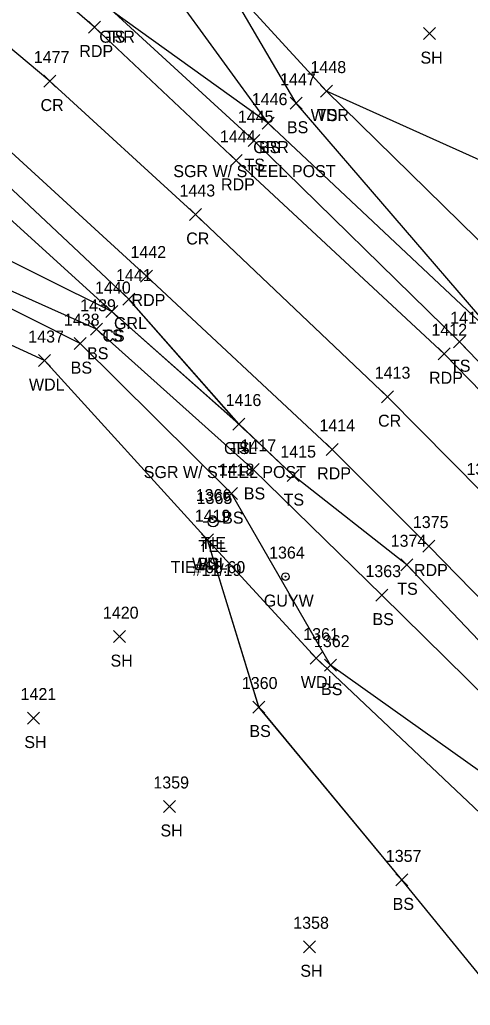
# Model space of a CAD drawing. Extents: x 1415642 to 1422021, y 544543 to 547232.
# Drawn here: x 1416185.4 to 1416260.5, y 546640.6 to 546804.9 of the extents above; entities that cross this region are included whole.
import ezdxf

# ---------------------------------------------------------------- set-up
doc = ezdxf.new("R2010")
doc.units = 0
for name, color, linetype in [('C_A', 7, 'Continuous'), ('C_C', 7, 'Continuous'), ('C_I', 7, 'Continuous'), ('CBP', 7, 'Continuous'), ('L_A', 7, 'Continuous'), ('L_I', 7, 'Continuous'), ('L_TIC', 7, 'Continuous'), ('LAWA', 7, 'Continuous'), ('LELB', 7, 'Continuous'), ('P_A', 7, 'Continuous'), ('P_I', 7, 'Continuous'), ('P_TIC', 7, 'Continuous'), ('PET', 7, 'Continuous'), ('PRC', 7, 'Continuous'), ('R_A', 7, 'Continuous'), ('R_C', 7, 'Continuous'), ('R_I', 7, 'Continuous'), ('R_TIC', 7, 'Continuous'), ('RGR', 7, 'Continuous'), ('U_A', 7, 'Continuous'), ('U_C', 7, 'Continuous'), ('U_I', 7, 'Continuous'), ('UP', 7, 'Continuous'), ('UPGW', 7, 'Continuous')]:
    doc.layers.add(name, color=color, linetype=linetype)

msp = doc.modelspace()

# ---------------------------------------------------------------- linework, layer by layer
at = {"layer": 'CBP'}
for radius in [0.625, 0.0833]:
    msp.add_circle((1416217.49, 546721.65), radius, dxfattribs=at)
at = {"layer": 'L_TIC'}
for points in [[(1416252.67, 546801.58), (1416254.67, 546803.58)], [(1416254.67, 546801.58), (1416252.67, 546803.58)], [(1416235.51, 546792), (1416237.51, 546794)], [(1416237.51, 546792), (1416235.51, 546794)], [(1416235.51, 546792), (1416237.51, 546794)], [(1416237.51, 546792), (1416235.51, 546794)], [(1416230.45, 546789.98), (1416232.45, 546791.98)], [(1416232.45, 546789.98), (1416230.45, 546791.98)], [(1416225.79, 546786.66), (1416227.79, 546788.66)], [(1416227.79, 546786.66), (1416225.79, 546788.66)], [(1416223.41, 546783.74), (1416225.41, 546785.74)], [(1416225.41, 546783.74), (1416223.41, 546785.74)], [(1416199.69, 546755.25), (1416201.69, 546757.25)], [(1416201.69, 546755.25), (1416199.69, 546757.25)], [(1416199.69, 546755.25), (1416201.69, 546757.25)], [(1416201.69, 546755.25), (1416199.69, 546757.25)], [(1416197.14, 546752.3), (1416199.14, 546754.3)], [(1416199.14, 546752.3), (1416197.14, 546754.3)], [(1416194.41, 546749.9), (1416196.41, 546751.9)], [(1416196.41, 546749.9), (1416194.41, 546751.9)], [(1416257.67, 546750.22), (1416259.67, 546752.22)], [(1416259.67, 546750.22), (1416257.67, 546752.22)], [(1416188.47, 546747.09), (1416190.47, 546749.09)], [(1416190.47, 546747.09), (1416188.47, 546749.09)], [(1416220.86, 546736.5), (1416222.86, 546738.5)], [(1416222.86, 546736.5), (1416220.86, 546738.5)], [(1416223.27, 546728.93), (1416225.27, 546730.93)], [(1416225.27, 546728.93), (1416223.27, 546730.93)], [(1416229.93, 546727.9), (1416231.93, 546729.9)], [(1416231.93, 546727.9), (1416229.93, 546729.9)], [(1416219.66, 546724.9), (1416221.66, 546726.9)], [(1416221.66, 546724.9), (1416219.66, 546726.9)], [(1416215.66, 546717.21), (1416217.66, 546719.21)], [(1416217.66, 546717.21), (1416215.66, 546719.21)], [(1416215.66, 546717.21), (1416217.66, 546719.21)], [(1416217.66, 546717.21), (1416215.66, 546719.21)], [(1416248.88, 546713.04), (1416250.88, 546715.04)], [(1416250.88, 546713.04), (1416248.88, 546715.04)], [(1416244.72, 546707.98), (1416246.72, 546709.98)], [(1416246.72, 546707.98), (1416244.72, 546709.98)], [(1416201, 546701.06), (1416203, 546703.06)], [(1416203, 546701.06), (1416201, 546703.06)], [(1416233.79, 546697.48), (1416235.79, 546699.48)], [(1416235.79, 546697.48), (1416233.79, 546699.48)], [(1416236.14, 546696.31), (1416238.14, 546698.31)], [(1416238.14, 546696.31), (1416236.14, 546698.31)], [(1416224.2, 546689.33), (1416226.2, 546691.33)], [(1416226.2, 546689.33), (1416224.2, 546691.33)], [(1416186.63, 546687.49), (1416188.63, 546689.49)], [(1416188.63, 546687.49), (1416186.63, 546689.49)], [(1416209.34, 546672.75), (1416211.34, 546674.75)], [(1416211.34, 546672.75), (1416209.34, 546674.75)], [(1416248.08, 546660.51), (1416250.08, 546662.51)], [(1416250.08, 546660.51), (1416248.08, 546662.51)], [(1416232.64, 546649.36), (1416234.64, 546651.36)], [(1416234.64, 546649.36), (1416232.64, 546651.36)]]:
    msp.add_lwpolyline(points, dxfattribs=at)
at = {"layer": 'LAWA'}
for points in [[(1416278.11, 546774.25), (1416236.51, 546793), (1416219.21, 546811.88)], [(1416278.12, 546774.25), (1416236.51, 546793), (1416219.21, 546811.88)], [(1416366.86, 546544.85), (1416337.81, 546578.41), (1416315.28, 546603.5), (1416281.6, 546646.05), (1416263.12, 546671.71), (1416234.79, 546698.48), (1416216.66, 546718.21), (1416189.47, 546748.09), (1416170.48, 546756.81)], [(1416366.86, 546544.85), (1416337.81, 546578.41), (1416315.28, 546603.5), (1416281.6, 546646.05), (1416263.12, 546671.71), (1416234.8, 546698.48), (1416216.66, 546718.21), (1416189.46, 546748.09), (1416170.49, 546756.81)]]:
    msp.add_lwpolyline(points, dxfattribs=at)
at = {"layer": 'LELB'}
for points in [[(1416200.69, 546756.25), (1416177.76, 546767.63), (1416166.72, 546775.57), (1416158.94, 546780.74), (1416149.8, 546790.95), (1416145.27, 546792.19), (1416135.47, 546803.24), (1416119.09, 546819.38), (1416087.86, 546845.73), (1416058.66, 546867.92), (1416017.63, 546898.15), (1415975.94, 546926.54), (1415961.59, 546937.35), (1415930.25, 546967.22), (1415904.85, 546987.6), (1415883.27, 547005.7), (1415850.56, 547030.99), (1415821.69, 547055.02)], [(1416200.69, 546756.25), (1416177.77, 546767.63), (1416166.72, 546775.57), (1416158.93, 546780.74), (1416149.8, 546790.95), (1416145.28, 546792.19), (1416135.47, 546803.24), (1416119.09, 546819.38), (1416087.87, 546845.73), (1416058.67, 546867.92), (1416017.63, 546898.16), (1415975.95, 546926.55), (1415961.6, 546937.34), (1415930.25, 546967.22), (1415904.86, 546987.6), (1415883.28, 547005.7), (1415850.57, 547030.99), (1415821.7, 547055.02)], [(1416413.88, 546519.84), (1416385.73, 546558.12), (1416356.85, 546595.36), (1416336.82, 546621.39), (1416300.66, 546661.66), (1416278.22, 546684.25), (1416249.88, 546714.04), (1416230.93, 546728.9), (1416221.86, 546737.5), (1416200.69, 546756.25), (1416176.24, 546778.44), (1416157.26, 546793.38), (1416140.02, 546808.9), (1416121.84, 546825.58), (1416090.2, 546848.7), (1416061.67, 546872.28), (1416021.03, 546902.96), (1415979.27, 546932.57), (1415964.6, 546940.59)], [(1416413.88, 546519.84), (1416385.73, 546558.12), (1416356.85, 546595.36), (1416336.82, 546621.39), (1416300.66, 546661.66), (1416278.22, 546684.25), (1416249.88, 546714.04), (1416230.93, 546728.9), (1416221.87, 546737.51), (1416200.69, 546756.25), (1416176.24, 546778.44), (1416157.26, 546793.38), (1416140.03, 546808.9), (1416121.84, 546825.58), (1416090.21, 546848.7), (1416061.68, 546872.28), (1416021.04, 546902.96), (1415979.28, 546932.57), (1415964.61, 546940.59)], [(1416307.15, 546711.36), (1416298.6, 546718.22), (1416262.67, 546753.94), (1416226.79, 546787.66), (1416210.45, 546810.14), (1416201.52, 546824.86), (1416194.8, 546838.18), (1416185.88, 546835.28), (1416179.92, 546838.46), (1416184.98, 546843.17), (1416189.86, 546849.7)], [(1416307.15, 546711.36), (1416298.6, 546718.22), (1416262.67, 546753.94), (1416226.79, 546787.66), (1416210.45, 546810.14), (1416201.53, 546824.86), (1416194.8, 546838.18), (1416185.88, 546835.28), (1416179.92, 546838.45), (1416184.98, 546843.16), (1416189.86, 546849.7)], [(1416313.42, 546715.93), (1416294.82, 546728.93), (1416263.75, 546753.42), (1416231.45, 546790.98), (1416219.21, 546811.88), (1416212.8, 546833.85)], [(1416313.42, 546715.93), (1416294.82, 546728.93), (1416263.75, 546753.42), (1416231.45, 546790.98), (1416219.21, 546811.88), (1416212.8, 546833.84)], [(1416462.64, 546496.11), (1416437.87, 546538.89), (1416411.19, 546576.82), (1416382.17, 546614.17), (1416360.8, 546639.39), (1416323.65, 546683.15), (1416301.53, 546707.03), (1416273.6, 546735.69), (1416258.67, 546751.22), (1416224.41, 546784.74), (1416201.13, 546806.07), (1416169.09, 546832.26)], [(1416462.64, 546496.11), (1416437.87, 546538.89), (1416411.18, 546576.82), (1416382.17, 546614.17), (1416360.8, 546639.39), (1416323.65, 546683.15), (1416301.53, 546707.03), (1416273.6, 546735.69), (1416258.67, 546751.22), (1416224.4, 546784.74), (1416201.13, 546806.07), (1416169.09, 546832.26)], [(1416308.55, 546724.26), (1416297.12, 546732.13), (1416269.94, 546760.18), (1416236.51, 546793)], [(1416308.55, 546724.26), (1416297.12, 546732.13), (1416269.94, 546760.18), (1416236.51, 546793)], [(1416578, 546177.77), (1416578.55, 546199.27), (1416573.9, 546214.14), (1416552.43, 546269), (1416536.22, 546304.5), (1416520.22, 546335.71), (1416500.65, 546371.21), (1416484.25, 546405.14), (1416455.06, 546455.78), (1416435.93, 546486.65), (1416412.14, 546519.01), (1416383.64, 546557.13), (1416352.74, 546592.54), (1416331.82, 546618.14), (1416293.94, 546655.61), (1416274.22, 546680.91), (1416245.72, 546708.98), (1416224.27, 546729.93), (1416198.14, 546753.3), (1416170.94, 546765.48), (1416158.5, 546767.31), (1416141.08, 546772.75), (1416136.01, 546776.95), (1416129, 546780.64)], [(1416578, 546177.77), (1416578.55, 546199.27), (1416573.9, 546214.14), (1416552.42, 546269.01), (1416536.22, 546304.5), (1416520.22, 546335.71), (1416500.65, 546371.22), (1416484.25, 546405.15), (1416455.06, 546455.79), (1416435.93, 546486.65), (1416412.14, 546519.01), (1416383.65, 546557.13), (1416352.74, 546592.54), (1416331.82, 546618.14), (1416293.94, 546655.62), (1416274.22, 546680.91), (1416245.72, 546708.98), (1416224.27, 546729.93), (1416198.14, 546753.3), (1416170.94, 546765.48), (1416158.51, 546767.31), (1416141.09, 546772.75), (1416136.01, 546776.96), (1416129.01, 546780.64)], [(1416503.76, 546247.98), (1416498.74, 546274.69), (1416501.23, 546308.66), (1416502.98, 546324.04), (1416489.47, 546365.32), (1416480.57, 546403.46), (1416453.11, 546455.02), (1416433.2, 546484.78), (1416409.26, 546516.78), (1416378.25, 546552.92), (1416343.61, 546583.91), (1416327.57, 546614.09), (1416289.4, 546651.59), (1416267.58, 546675.69), (1416237.14, 546697.31), (1416220.66, 546725.9), (1416195.41, 546750.9), (1416170.78, 546763.33), (1416158.82, 546764.49), (1416140.16, 546770.72), (1416135.4, 546775.05), (1416128.27, 546778.63)], [(1416503.76, 546247.98), (1416498.74, 546274.69), (1416501.24, 546308.65), (1416502.98, 546324.03), (1416489.47, 546365.32), (1416480.57, 546403.46), (1416453.11, 546455.02), (1416433.2, 546484.78), (1416409.26, 546516.79), (1416378.25, 546552.92), (1416343.61, 546583.91), (1416327.58, 546614.09), (1416289.4, 546651.59), (1416267.58, 546675.69), (1416237.14, 546697.31), (1416220.66, 546725.9), (1416195.42, 546750.9), (1416170.78, 546763.33), (1416158.81, 546764.5), (1416140.16, 546770.72), (1416135.4, 546775.05), (1416128.28, 546778.62)], [(1416315.28, 546603.5), (1416270.97, 546634.69), (1416249.08, 546661.51), (1416225.2, 546690.33), (1416216.66, 546718.21)], [(1416315.28, 546603.5), (1416270.97, 546634.69), (1416249.08, 546661.51), (1416225.21, 546690.34), (1416216.66, 546718.21)]]:
    msp.add_lwpolyline(points, dxfattribs=at)
at = {"layer": 'P_TIC'}
for points in [[(1416196.8, 546802.68), (1416198.8, 546804.68)], [(1416198.8, 546802.68), (1416196.8, 546804.68)], [(1416189.4, 546793.67), (1416191.4, 546795.67)], [(1416191.4, 546793.67), (1416189.4, 546795.67)], [(1416220.42, 546780.44), (1416222.42, 546782.44)], [(1416222.42, 546780.44), (1416220.42, 546782.44)], [(1416213.68, 546771.43), (1416215.68, 546773.43)], [(1416215.68, 546771.43), (1416213.68, 546773.43)], [(1416205.51, 546761.17), (1416207.51, 546763.17)], [(1416207.51, 546761.17), (1416205.51, 546763.17)], [(1416255.1, 546748.21), (1416257.1, 546750.21)], [(1416257.1, 546748.21), (1416255.1, 546750.21)], [(1416245.66, 546741.06), (1416247.66, 546743.06)], [(1416247.66, 546741.06), (1416245.66, 546743.06)], [(1416236.44, 546732.28), (1416238.44, 546734.28)], [(1416238.44, 546732.28), (1416236.44, 546734.28)], [(1416252.58, 546716.16), (1416254.58, 546718.16)], [(1416254.58, 546716.16), (1416252.58, 546718.16)]]:
    msp.add_lwpolyline(points, dxfattribs=at)
at = {"layer": 'PET'}
for points in [[(1416435.56, 546537.44), (1416408.53, 546574.61), (1416379.54, 546611.97), (1416358.62, 546637.86), (1416320.38, 546681.18), (1416299.04, 546704.62), (1416270.68, 546734.26), (1416256.1, 546749.21), (1416221.42, 546781.44), (1416197.8, 546803.68), (1416167.45, 546829.93), (1416146.9, 546847.39), (1416116.66, 546870.72), (1416088.42, 546892.72), (1416062.97, 546911.59), (1416031.6, 546935.61), (1415998.08, 546959.73), (1415969.06, 546981.93), (1415936.64, 547006.92)], [(1416435.56, 546537.44), (1416408.53, 546574.62), (1416379.54, 546611.97), (1416358.63, 546637.85), (1416320.38, 546681.18), (1416299.04, 546704.62), (1416270.69, 546734.26), (1416256.1, 546749.21), (1416221.42, 546781.44), (1416197.8, 546803.68), (1416167.45, 546829.93), (1416146.9, 546847.38), (1416116.66, 546870.72), (1416088.42, 546892.72), (1416062.98, 546911.58), (1416031.6, 546935.61), (1415998.08, 546959.73), (1415969.07, 546981.93), (1415936.65, 547006.92)], [(1416417.68, 546520.98), (1416388.9, 546560.28), (1416359.4, 546597.75), (1416339.06, 546622.92), (1416303.08, 546664.45), (1416282.37, 546687.64), (1416253.58, 546717.16), (1416237.44, 546733.28), (1416206.51, 546762.17), (1416181.86, 546784.67), (1416151.94, 546810.47), (1416130.39, 546828.26), (1416101.49, 546851.34), (1416072.78, 546874.03), (1416047.41, 546892.82), (1416017.81, 546915.59), (1415982.21, 546942.39), (1415954.4, 546964.56)], [(1416417.68, 546520.98), (1416388.9, 546560.28), (1416359.4, 546597.76), (1416339.06, 546622.93), (1416303.08, 546664.45), (1416282.37, 546687.65), (1416253.58, 546717.16), (1416237.44, 546733.28), (1416206.51, 546762.17), (1416181.87, 546784.67), (1416151.94, 546810.47), (1416130.39, 546828.26), (1416101.49, 546851.34), (1416072.78, 546874.03), (1416047.41, 546892.82), (1416017.81, 546915.59), (1415982.21, 546942.39), (1415954.4, 546964.56)]]:
    msp.add_lwpolyline(points, dxfattribs=at)
at = {"layer": 'PRC'}
for points in [[(1416425.29, 546532.23), (1416399.16, 546568.17), (1416370.34, 546605), (1416349.98, 546630.03), (1416312.55, 546673.44), (1416291.21, 546696.63), (1416262.58, 546725.99), (1416246.66, 546742.06), (1416214.68, 546772.43), (1416190.4, 546794.67), (1416160.38, 546819.82), (1416139.01, 546837.64), (1416109.6, 546860.71), (1416080.51, 546883.13), (1416051.44, 546902.01), (1416024.84, 546926.07), (1415989.92, 546951.67), (1415962.46, 546973.18)], [(1416425.29, 546532.24), (1416399.16, 546568.17), (1416370.35, 546605), (1416349.98, 546630.03), (1416312.55, 546673.45), (1416291.21, 546696.63), (1416262.58, 546725.99), (1416246.66, 546742.06), (1416214.67, 546772.43), (1416190.4, 546794.67), (1416160.38, 546819.82), (1416139.01, 546837.64), (1416109.6, 546860.71), (1416080.51, 546883.13), (1416051.45, 546902.01), (1416024.84, 546926.07), (1415989.92, 546951.68), (1415962.46, 546973.18)]]:
    msp.add_lwpolyline(points, dxfattribs=at)
at = {"layer": 'R_TIC'}
for points in [[(1416225.79, 546786.66), (1416227.79, 546788.66)], [(1416227.79, 546786.66), (1416225.79, 546788.66)], [(1416202.53, 546757.32), (1416204.53, 546759.32)], [(1416204.53, 546757.32), (1416202.53, 546759.32)], [(1416220.86, 546736.5), (1416222.86, 546738.5)], [(1416222.86, 546736.5), (1416220.86, 546738.5)]]:
    msp.add_lwpolyline(points, dxfattribs=at)
at = {"layer": 'RGR'}
for points in [[(1416226.79, 546787.66), (1416201.13, 546806.07), (1416168.8, 546834.69), (1416149.29, 546850.1), (1416119.32, 546873.14), (1416091.47, 546896.23), (1416072.68, 546914.46)], [(1416226.79, 546787.66), (1416201.13, 546806.07), (1416168.81, 546834.68), (1416149.29, 546850.1), (1416119.32, 546873.14), (1416091.47, 546896.23), (1416072.68, 546914.46)], [(1416221.86, 546737.5), (1416203.53, 546758.32), (1416178.59, 546781.72), (1416160.13, 546797.47)], [(1416221.87, 546737.51), (1416203.53, 546758.32), (1416178.59, 546781.72), (1416160.13, 546797.47)]]:
    msp.add_lwpolyline(points, dxfattribs=at)
at = {"layer": 'UP'}
for p, q in [((1416215.93, 546721.18), (1416216.76, 546721.18)), ((1416217.59, 546721.18), (1416217.59, 546721.18)), ((1416219.26, 546721.18), (1416218.43, 546721.18)), ((1416218.43, 546721.18), (1416218.43, 546721.18)), ((1416219.26, 546721.18), (1416219.26, 546721.18))]:
    msp.add_line(p, q, dxfattribs=at)
msp.add_circle((1416217.59, 546721.18), 0.833, dxfattribs=at)
at = {"layer": 'UPGW'}
for radius in [0.625, 0.0833]:
    msp.add_circle((1416229.66, 546712.07), radius, dxfattribs=at)

# ---------------------------------------------------------------- texts
at = {"layer": 'C_A'}
msp.add_text('TIE', height=2, dxfattribs=at).set_placement((1416215.57, 546716.65))
at = {"layer": 'C_C'}
msp.add_text('TIE=65.60', height=2, dxfattribs=at).set_placement((1416210.53, 546712.65))
at = {"layer": 'C_I'}
msp.add_text('1366', height=2, dxfattribs=at).set_placement((1416214.69, 546724.65))
at = {"layer": 'L_A'}
for s, p in [('TS', (1416199.54, 546801.07)), ('SH', (1416252.16, 546797.58)), ('WDR', (1416233.87, 546788)), ('TS', (1416234.92, 546788)), ('BS', (1416229.89, 546785.98)), ('BS', (1416225.23, 546782.66)), ('TS', (1416222.82, 546779.74)), ('TS', (1416199.1, 546751.25)), ('CS', (1416199.13, 546751.25)), ('BS', (1416196.58, 546748.3)), ('TS', (1416257.08, 546746.22)), ('BS', (1416193.85, 546745.9)), ('WDL', (1416186.89, 546743.09)), ('TS', (1416220.27, 546732.5)), ('BS', (1416222.71, 546724.93)), ('TS', (1416229.34, 546723.9)), ('BS', (1416219.1, 546720.9)), ('WDL', (1416214.08, 546713.21)), ('BS', (1416215.1, 546713.21)), ('TS', (1416248.29, 546709.04)), ('BS', (1416244.16, 546703.98)), ('SH', (1416200.49, 546697.06)), ('WDL', (1416232.21, 546693.48)), ('BS', (1416235.58, 546692.31)), ('BS', (1416223.64, 546685.33)), ('SH', (1416186.12, 546683.49)), ('SH', (1416208.82, 546668.75)), ('BS', (1416247.52, 546656.51)), ('SH', (1416232.13, 546645.36))]:
    msp.add_text(s, height=2, dxfattribs=at).set_placement(p)
at = {"layer": 'L_I'}
for s, p in [('1448', (1416233.82, 546796)), ('1448', (1416233.82, 546796)), ('1447', (1416228.76, 546793.98)), ('1446', (1416224.04, 546790.66)), ('1445', (1416221.71, 546787.74)), ('1440', (1416197.91, 546759.25)), ('1440', (1416197.91, 546759.25)), ('1439', (1416195.44, 546756.3)), ('1438', (1416192.72, 546753.9)), ('1411', (1416257.11, 546754.22)), ('1437', (1416186.78, 546751.09)), ('1416', (1416219.68, 546740.5)), ('1417', (1416222.15, 546732.93)), ('1415', (1416228.8, 546731.9)), ('1418', (1416218.53, 546728.9)), ('1419', (1416214.53, 546721.21)), ('1419', (1416214.53, 546721.21)), ('1374', (1416247.19, 546717.04)), ('1363', (1416242.98, 546711.98)), ('1420', (1416199.22, 546705.06)), ('1361', (1416232.62, 546701.48)), ('1362', (1416234.4, 546700.31)), ('1360', (1416222.38, 546693.33)), ('1421', (1416185.5, 546691.49)), ('1359', (1416207.63, 546676.75)), ('1357', (1416246.38, 546664.51)), ('1358', (1416230.95, 546653.36))]:
    msp.add_text(s, height=2, dxfattribs=at).set_placement(p)
at = {"layer": 'P_A'}
for s, p in [('RDP', (1416195.29, 546798.68)), ('CR', (1416188.83, 546789.67)), ('RDP', (1416218.91, 546776.44)), ('CR', (1416213.11, 546767.43)), ('RDP', (1416203.99, 546757.17)), ('RDP', (1416253.59, 546744.21)), ('CR', (1416245.09, 546737.06)), ('RDP', (1416234.93, 546728.28)), ('RDP', (1416251.07, 546712.16))]:
    msp.add_text(s, height=2, dxfattribs=at).set_placement(p)
at = {"layer": 'P_I'}
for s, p in [('1477', (1416187.7, 546797.67)), ('1444', (1416218.73, 546784.44)), ('1443', (1416211.99, 546775.43)), ('1442', (1416203.81, 546765.17)), ('1412', (1416253.98, 546752.21)), ('1413', (1416244.53, 546745.06)), ('1414', (1416235.31, 546736.28)), ('1376', (1416259.83, 546728.99)), ('1375', (1416250.89, 546720.16))]:
    msp.add_text(s, height=2, dxfattribs=at).set_placement(p)
at = {"layer": 'R_A'}
for s, p in [('GRR', (1416198.62, 546801.07)), ('GRR', (1416224.28, 546782.66)), ('GRL', (1416201.07, 546753.32)), ('GRL', (1416219.41, 546732.5))]:
    msp.add_text(s, height=2, dxfattribs=at).set_placement(p)
at = {"layer": 'R_C'}
for p in [(1416210.96, 546778.66), (1416206.03, 546728.5)]:
    msp.add_text('SGR W/ STEEL POST', height=2, dxfattribs=at).set_placement(p)
at = {"layer": 'R_I'}
for s, p in [('1446', (1416224.04, 546790.66)), ('1441', (1416201.4, 546761.32)), ('1416', (1416219.68, 546740.5))]:
    msp.add_text(s, height=2, dxfattribs=at).set_placement(p)
at = {"layer": 'U_A'}
for s, p in [('TEL', (1416215.15, 546716.18)), ('GUYW', (1416226.05, 546707.07))]:
    msp.add_text(s, height=2, dxfattribs=at).set_placement(p)
at = {"layer": 'U_C'}
msp.add_text('#11/19', height=2, dxfattribs=at).set_placement((1416214.15, 546712.18))
at = {"layer": 'U_I'}
for s, p in [('1365', (1416214.85, 546724.18)), ('1364', (1416226.92, 546715.07))]:
    msp.add_text(s, height=2, dxfattribs=at).set_placement(p)

doc.saveas('drawing.dxf')
